// Mitsubishi GX Works2 project: 定时器   PLC: FX3U/FX3UC

PROGRAM MAIN
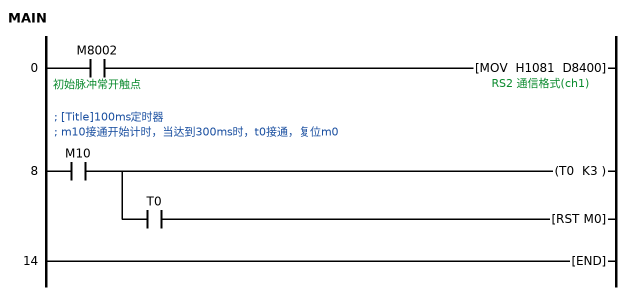
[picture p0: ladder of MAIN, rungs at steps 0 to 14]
0     LD      M8002  ; 初始脉冲常开触点
      MOV     H1081 D8400  ; RS2 通信格式(ch1)
; [Title]100ms定时器
; m10接通开始计时，当达到300ms时，t0接通，复位m0
8     LD      M10
      OUT     T0 K3
      AND     T0
      RST     M0
14    END
END_PROGRAM

// device comments not shown above
C10  ; CCD1拍照连续不良计数
C11  ; CCD2连续不良计数
